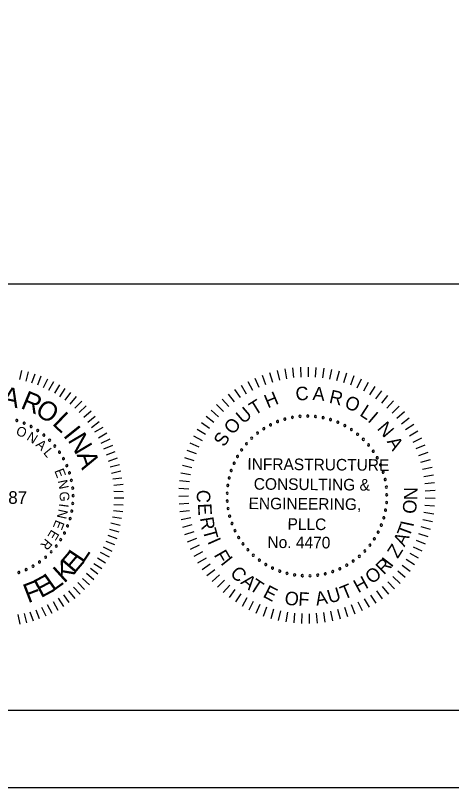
# Model space of a CAD drawing. Extents: x 1970675.2 to 1970711.3, y 796145.2 to 796167.2.
# Drawn here: x 1970699.687 to 1970702.503, y 796145.246 to 796150.229 of the extents above; entities that cross this region are included whole.
import ezdxf

# ---------------------------------------------------------------- set-up
doc = ezdxf.new("R2010")
doc.units = 0
for name, color, linetype in [('BR_BORDER LINES', 7, 'Continuous'), ('BR_TEXT', 7, 'Continuous'), ('Level 31', 7, 'Continuous')]:
    doc.layers.add(name, color=color, linetype=linetype)

msp = doc.modelspace()

# ---------------------------------------------------------------- linework, layer by layer
at = {"layer": 'BR_BORDER LINES'}
for p, q in [((1970697.8703, 796148.4964), (1970703.2355, 796148.4964)), ((1970677.0698, 796145.7463), (1970710.7358, 796145.7463))]:
    msp.add_line(p, q, dxfattribs=at)
at = {"layer": 'BR_TEXT'}
for p, q in [((1970699.7143, 796147.8794), (1970699.7285, 796147.9385)), ((1970701.4262, 796147.9473), (1970701.4372, 796147.8846)), ((1970701.4761, 796147.9545), (1970701.4834, 796147.8913)), ((1970701.5265, 796147.9587), (1970701.5298, 796147.8951)), ((1970701.5769, 796147.9597), (1970701.5764, 796147.8961)), ((1970701.6274, 796147.9577), (1970701.623, 796147.8942)), ((1970701.6776, 796147.9526), (1970701.6693, 796147.8895)), ((1970701.7274, 796147.9445), (1970701.7153, 796147.882)), ((1970699.7554, 796147.8688), (1970699.7713, 796147.9295)), ((1970699.7922, 796147.8582), (1970699.8141, 796147.9155)), ((1970699.8316, 796147.8449), (1970699.8535, 796147.9031)), ((1970701.2334, 796147.8887), (1970701.2593, 796147.8305)), ((1970701.2802, 796147.9077), (1970701.3025, 796147.8481)), ((1970701.328, 796147.9239), (1970701.3466, 796147.863)), ((1970701.3767, 796147.9371), (1970701.3916, 796147.8752)), ((1970701.7767, 796147.9333), (1970701.7608, 796147.8717)), ((1970701.8251, 796147.9192), (1970701.8055, 796147.8586)), ((1970701.8726, 796147.9021), (1970701.8494, 796147.8428)), ((1970699.8675, 796147.8275), (1970699.8954, 796147.883)), ((1970699.9034, 796147.81), (1970699.9347, 796147.8656)), ((1970699.941, 796147.7917), (1970699.9732, 796147.8455)), ((1970701.1439, 796147.8422), (1970701.1766, 796147.7876)), ((1970701.1879, 796147.8668), (1970701.2173, 796147.8103)), ((1970701.919, 796147.8822), (1970701.8922, 796147.8244)), ((1970701.9641, 796147.8594), (1970701.9338, 796147.8034)), ((1970699.9743, 796147.7674), (1970700.0082, 796147.8212)), ((1970700.0075, 796147.7457), (1970700.044, 796147.796)), ((1970701.1014, 796147.8149), (1970701.1374, 796147.7625)), ((1970702.0077, 796147.834), (1970701.974, 796147.78)), ((1970702.0497, 796147.8059), (1970702.0128, 796147.7541)), ((1970700.0399, 796147.7197), (1970700.0806, 796147.7691)), ((1970700.0715, 796147.6945), (1970700.1147, 796147.7388)), ((1970701.0217, 796147.7529), (1970701.0639, 796147.7052)), ((1970701.0606, 796147.7852), (1970701.0998, 796147.735)), ((1970702.0899, 796147.7754), (1970702.0499, 796147.7259)), ((1970702.1281, 796147.7424), (1970702.0852, 796147.6954)), ((1970700.0995, 796147.6668), (1970700.1428, 796147.7102)), ((1970700.9849, 796147.7184), (1970701.0299, 796147.6734)), ((1970702.1643, 796147.7072), (1970702.1186, 796147.6629)), ((1970700.1276, 796147.6357), (1970700.1752, 796147.6774)), ((1970700.1548, 796147.6037), (1970700.2015, 796147.6419)), ((1970700.9179, 796147.643), (1970700.968, 796147.6037)), ((1970700.9502, 796147.6817), (1970700.9979, 796147.6395)), ((1970702.1982, 796147.6699), (1970702.1499, 796147.6284)), ((1970700.1786, 796147.57), (1970700.2278, 796147.6091)), ((1970700.8879, 796147.6023), (1970700.9404, 796147.5662)), ((1970702.2299, 796147.6305), (1970702.1791, 796147.5921)), ((1970702.259, 796147.5893), (1970702.206, 796147.5541)), ((1970700.2006, 796147.5407), (1970700.2532, 796147.5729)), ((1970700.8605, 796147.5599), (1970700.9151, 796147.5271)), ((1970702.2856, 796147.5464), (1970702.2305, 796147.5145)), ((1970700.2226, 796147.5036), (1970700.2761, 796147.5349)), ((1970700.2404, 796147.4691), (1970700.2981, 796147.4961)), ((1970700.8358, 796147.5159), (1970700.8922, 796147.4865)), ((1970702.3095, 796147.5019), (1970702.2526, 796147.4734)), ((1970700.2581, 796147.4321), (1970700.315, 796147.4565)), ((1970700.8137, 796147.4705), (1970700.8719, 796147.4445)), ((1970702.3307, 796147.4561), (1970702.2722, 796147.4311)), ((1970700.2749, 796147.3933), (1970700.3318, 796147.4143)), ((1970700.7945, 796147.4238), (1970700.8541, 796147.4014)), ((1970702.3491, 796147.4091), (1970702.2891, 796147.3877)), ((1970700.2883, 796147.3529), (1970700.346, 796147.3747)), ((1970700.7782, 796147.3761), (1970700.839, 796147.3574)), ((1970702.3645, 796147.361), (1970702.3033, 796147.3433)), ((1970700.2984, 796147.3168), (1970700.3585, 796147.3308)), ((1970700.7648, 796147.3274), (1970700.8267, 796147.3124)), ((1970702.377, 796147.3121), (1970702.3148, 796147.2982)), ((1970700.3066, 796147.2746), (1970700.3668, 796147.2896)), ((1970700.3149, 796147.2385), (1970700.3741, 796147.2458)), ((1970700.7543, 796147.278), (1970700.817, 796147.2668)), ((1970702.3864, 796147.2625), (1970702.3236, 796147.2524)), ((1970700.3214, 796147.1973), (1970700.3824, 796147.2036)), ((1970700.747, 796147.228), (1970700.8102, 796147.2207)), ((1970702.3929, 796147.2124), (1970702.3295, 796147.2062)), ((1970700.3228, 796147.1578), (1970700.3829, 796147.1573)), ((1970700.7426, 796147.1777), (1970700.8062, 796147.1743)), ((1970702.3963, 796147.1621), (1970702.3326, 796147.1597)), ((1970700.325, 796147.1166), (1970700.3859, 796147.1161)), ((1970700.7414, 796147.1273), (1970700.8051, 796147.1277)), ((1970702.3965, 796147.1116), (1970702.3329, 796147.1131)), ((1970700.3221, 796147.0737), (1970700.3822, 796147.0715)), ((1970700.7432, 796147.0768), (1970700.8067, 796147.0812)), ((1970702.3938, 796147.0612), (1970702.3303, 796147.0666)), ((1970700.3129, 796146.994), (1970700.372, 796146.984)), ((1970700.32, 796147.0351), (1970700.3809, 796147.0269)), ((1970700.7481, 796147.0266), (1970700.8113, 796147.0348)), ((1970702.3879, 796147.011), (1970702.3249, 796147.0203)), ((1970700.3039, 796146.9546), (1970700.3639, 796146.9403)), ((1970700.7561, 796146.9767), (1970700.8186, 796146.9888)), ((1970700.7671, 796146.9275), (1970700.8287, 796146.9433)), ((1970702.379, 796146.9613), (1970702.3167, 796146.9744)), ((1970700.295, 796146.9126), (1970700.3549, 796146.8975)), ((1970700.781, 796146.8789), (1970700.8416, 796146.8985)), ((1970702.3671, 796146.9123), (1970702.3057, 796146.9291)), ((1970700.2844, 796146.8758), (1970700.3417, 796146.8538)), ((1970700.7979, 796146.8314), (1970700.8572, 796146.8546)), ((1970702.3522, 796146.864), (1970702.2919, 796146.8846)), ((1970700.2529, 796146.8005), (1970700.3093, 796146.7726)), ((1970700.2704, 796146.8373), (1970700.3268, 796146.8153)), ((1970700.8177, 796146.7849), (1970700.8755, 796146.8117)), ((1970702.3138, 796146.7707), (1970702.2564, 796146.7985)), ((1970702.3344, 796146.8168), (1970702.2755, 796146.841)), ((1970700.2346, 796146.7646), (1970700.2918, 796146.7341)), ((1970700.8403, 796146.7397), (1970700.8963, 796146.77)), ((1970702.2904, 796146.726), (1970702.2348, 796146.7572)), ((1970700.2162, 796146.7279), (1970700.2692, 796146.6957)), ((1970700.8655, 796146.696), (1970700.9196, 796146.7297)), ((1970702.2643, 796146.6828), (1970702.2107, 796146.7173)), ((1970700.1711, 796146.6622), (1970700.2197, 796146.6248)), ((1970700.1936, 796146.6911), (1970700.2457, 796146.659)), ((1970700.8934, 796146.654), (1970700.9453, 796146.6908)), ((1970700.9238, 796146.6137), (1970700.9734, 796146.6536)), ((1970702.2356, 796146.6412), (1970702.1843, 796146.6789)), ((1970700.119, 796146.5956), (1970700.1659, 796146.5541)), ((1970700.1468, 796146.6289), (1970700.1928, 796146.589)), ((1970700.9566, 796146.5753), (1970701.0037, 796146.6182)), ((1970702.1709, 796146.5638), (1970702.1245, 796146.6074)), ((1970702.2044, 796146.6015), (1970702.1555, 796146.6423)), ((1970700.0905, 796146.5701), (1970700.133, 796146.5243)), ((1970700.9917, 796146.539), (1970701.0361, 796146.5847)), ((1970701.0289, 796146.5049), (1970701.0704, 796146.5532)), ((1970702.0973, 796146.4948), (1970702.0566, 796146.5437)), ((1970702.1351, 796146.5281), (1970702.0915, 796146.5745)), ((1970700.03, 796146.5149), (1970700.0699, 796146.4673)), ((1970700.0619, 796146.5403), (1970700.1044, 796146.4936)), ((1970701.0682, 796146.4731), (1970701.1066, 796146.5239)), ((1970701.1093, 796146.4438), (1970701.1446, 796146.4968)), ((1970702.0574, 796146.4637), (1970702.0198, 796146.5151)), ((1970699.9299, 796146.4462), (1970699.9612, 796146.3918)), ((1970699.9635, 796146.4682), (1970699.9966, 796146.4156)), ((1970699.9972, 796146.4894), (1970700.0328, 796146.441)), ((1970701.1521, 796146.4171), (1970701.1841, 796146.4721)), ((1970701.1965, 796146.393), (1970701.225, 796146.4499)), ((1970701.9276, 796146.386), (1970701.9, 796146.4434)), ((1970701.9725, 796146.4093), (1970701.9414, 796146.4648)), ((1970702.0158, 796146.4352), (1970701.9813, 796146.4888)), ((1970699.8558, 796146.4099), (1970699.8827, 796146.3539)), ((1970699.8919, 796146.4267), (1970699.9224, 796146.3707)), ((1970701.2422, 796146.3716), (1970701.2673, 796146.4302)), ((1970701.2892, 796146.3531), (1970701.3106, 796146.4131)), ((1970701.3372, 796146.3375), (1970701.3549, 796146.3986)), ((1970701.7859, 796146.3332), (1970701.7691, 796146.3947)), ((1970701.8342, 796146.3479), (1970701.8137, 796146.4082)), ((1970701.8815, 796146.3656), (1970701.8574, 796146.4245)), ((1970699.7018, 796146.3631), (1970699.715, 796146.3012)), ((1970699.743, 796146.3696), (1970699.758, 796146.3103)), ((1970699.78, 796146.3813), (1970699.801, 796146.3228)), ((1970699.8196, 796146.393), (1970699.8406, 796146.3362)), ((1970701.386, 796146.3248), (1970701.4001, 796146.3869)), ((1970701.4356, 796146.3152), (1970701.4458, 796146.378)), ((1970701.4856, 796146.3086), (1970701.492, 796146.3719)), ((1970701.536, 796146.305), (1970701.5385, 796146.3686)), ((1970701.5865, 796146.3045), (1970701.5851, 796146.3682)), ((1970701.6369, 796146.3071), (1970701.6316, 796146.3706)), ((1970701.6871, 796146.3128), (1970701.6779, 796146.3758)), ((1970701.7368, 796146.3215), (1970701.7238, 796146.3838))]:
    msp.add_line(p, q, dxfattribs=at)
for centre, start, end in [((1970701.4753, 796147.635), 10.6038, 190.6038), ((1970701.5247, 796147.6417), 5.0653, 185.0653), ((1970701.5247, 796147.6417), 185.0653, 5.0653), ((1970701.5745, 796147.6436), 359.5268, 179.5268), ((1970701.5745, 796147.6436), 179.5268, 359.5268), ((1970701.6242, 796147.6407), 173.9884, 353.9884), ((1970701.6242, 796147.6407), 353.9884, 173.9884), ((1970701.6735, 796147.6329), 348.4499, 168.4499), ((1970699.696, 796147.6149), 162.9114, 342.9114), ((1970699.696, 796147.6149), 342.9114, 162.9114), ((1970699.7429, 796147.5979), 157.373, 337.373), ((1970699.7429, 796147.5979), 337.373, 157.373), ((1970701.3343, 796147.587), 27.2191, 207.2191), ((1970701.3343, 796147.587), 207.2191, 27.2191), ((1970701.3797, 796147.6075), 21.6807, 201.6807), ((1970701.3797, 796147.6075), 201.6807, 21.6807), ((1970701.4268, 796147.6235), 16.1422, 196.1422), ((1970701.4268, 796147.6235), 196.1422, 16.1422), ((1970701.4753, 796147.635), 190.6038, 10.6038), ((1970701.6735, 796147.6329), 168.4499, 348.4499), ((1970701.7217, 796147.6205), 162.9114, 342.9114), ((1970701.7217, 796147.6205), 342.9114, 162.9114), ((1970701.7686, 796147.6035), 157.373, 337.373), ((1970701.7686, 796147.6035), 337.373, 157.373), ((1970701.8135, 796147.582), 331.8345, 151.8345), ((1970699.7878, 796147.5764), 151.8345, 331.8345), ((1970699.7878, 796147.5764), 331.8345, 151.8345), ((1970699.8305, 796147.5507), 146.2961, 326.2961), ((1970699.8305, 796147.5507), 326.2961, 146.2961), ((1970701.2504, 796147.5333), 38.2961, 218.2961), ((1970701.291, 796147.5621), 32.7576, 212.7576), ((1970701.291, 796147.5621), 212.7576, 32.7576), ((1970701.8135, 796147.582), 151.8345, 331.8345), ((1970701.8562, 796147.5563), 146.2961, 326.2961), ((1970701.8562, 796147.5563), 326.2961, 146.2961), ((1970699.8705, 796147.521), 140.7576, 320.7576), ((1970699.8705, 796147.521), 320.7576, 140.7576), ((1970699.9075, 796147.4876), 135.2191, 315.2191), ((1970699.9075, 796147.4876), 315.2191, 135.2191), ((1970701.2128, 796147.5006), 43.8345, 223.8345), ((1970701.2128, 796147.5006), 223.8345, 43.8345), ((1970701.2504, 796147.5333), 218.2961, 38.2961), ((1970701.8962, 796147.5266), 140.7576, 320.7576), ((1970701.8962, 796147.5266), 320.7576, 140.7576), ((1970701.9332, 796147.4932), 135.2191, 315.2191), ((1970701.9332, 796147.4932), 315.2191, 135.2191), ((1970699.9411, 796147.4508), 129.6807, 309.6807), ((1970699.9411, 796147.4508), 309.6807, 129.6807), ((1970701.1785, 796147.4645), 49.373, 229.373), ((1970701.1785, 796147.4645), 229.373, 49.373), ((1970701.9668, 796147.4564), 129.6807, 309.6807), ((1970701.9668, 796147.4564), 309.6807, 129.6807), ((1970699.9709, 796147.4109), 124.1422, 304.1422), ((1970699.9709, 796147.4109), 304.1422, 124.1422), ((1970701.1211, 796147.3831), 60.4499, 240.4499), ((1970701.1478, 796147.4252), 54.9114, 234.9114), ((1970701.1478, 796147.4252), 234.9114, 54.9114), ((1970701.9966, 796147.4165), 124.1422, 304.1422), ((1970701.9966, 796147.4165), 304.1422, 124.1422), ((1970699.9968, 796147.3683), 118.6038, 298.6038), ((1970699.9968, 796147.3683), 298.6038, 118.6038), ((1970701.0986, 796147.3387), 65.9884, 245.9884), ((1970701.0986, 796147.3387), 245.9884, 65.9884), ((1970701.1211, 796147.3831), 240.4499, 60.4499), ((1970702.0225, 796147.3739), 118.6038, 298.6038), ((1970702.0225, 796147.3739), 298.6038, 118.6038), ((1970700.0184, 796147.3234), 113.0653, 293.0653), ((1970700.0184, 796147.3234), 293.0653, 113.0653), ((1970701.0804, 796147.2923), 71.5268, 251.5268), ((1970701.0804, 796147.2923), 251.5268, 71.5268), ((1970702.0441, 796147.329), 113.0653, 293.0653), ((1970702.0441, 796147.329), 293.0653, 113.0653), ((1970700.0356, 796147.2766), 107.5268, 287.5268), ((1970700.0356, 796147.2766), 287.5268, 107.5268), ((1970701.0668, 796147.2443), 77.0653, 257.0653), ((1970701.0668, 796147.2443), 257.0653, 77.0653), ((1970702.0613, 796147.2822), 107.5268, 287.5268), ((1970702.0613, 796147.2822), 287.5268, 107.5268), ((1970702.0739, 796147.234), 101.9884, 281.9884), ((1970702.0739, 796147.234), 281.9884, 101.9884), ((1970700.0482, 796147.2284), 101.9884, 281.9884), ((1970700.0482, 796147.2284), 281.9884, 101.9884), ((1970701.0579, 796147.1953), 82.6038, 262.6038), ((1970701.0579, 796147.1953), 262.6038, 82.6038), ((1970702.0818, 796147.1848), 96.4499, 276.4499), ((1970702.0818, 796147.1848), 276.4499, 96.4499), ((1970700.0561, 796147.1792), 96.4499, 276.4499), ((1970700.0561, 796147.1792), 276.4499, 96.4499), ((1970701.0538, 796147.1456), 88.1422, 268.1422), ((1970701.0538, 796147.1456), 268.1422, 88.1422), ((1970702.0849, 796147.1351), 90.9114, 270.9114), ((1970702.0849, 796147.1351), 270.9114, 90.9114), ((1970700.0592, 796147.1295), 90.9114, 270.9114), ((1970700.0592, 796147.1295), 270.9114, 90.9114), ((1970701.0545, 796147.0958), 93.6807, 273.6807), ((1970701.0545, 796147.0958), 273.6807, 93.6807), ((1970702.0832, 796147.0853), 85.373, 265.373), ((1970702.0832, 796147.0853), 265.373, 85.373), ((1970700.0575, 796147.0797), 85.373, 265.373), ((1970700.0575, 796147.0797), 265.373, 85.373), ((1970701.06, 796147.0463), 99.2191, 279.2191), ((1970701.06, 796147.0463), 279.2191, 99.2191), ((1970702.0766, 796147.0359), 79.8345, 259.8345), ((1970702.0766, 796147.0359), 259.8345, 79.8345), ((1970700.0509, 796147.0303), 79.8345, 259.8345), ((1970700.0509, 796147.0303), 259.8345, 79.8345), ((1970701.0703, 796146.9975), 104.7576, 284.7576), ((1970701.0703, 796146.9975), 284.7576, 104.7576), ((1970702.0654, 796146.9873), 74.2961, 254.2961), ((1970702.0654, 796146.9873), 254.2961, 74.2961), ((1970700.0238, 796146.9345), 68.7576, 248.7576), ((1970700.0397, 796146.9817), 74.2961, 254.2961), ((1970700.0397, 796146.9817), 254.2961, 74.2961), ((1970701.0852, 796146.95), 110.2961, 290.2961), ((1970701.0852, 796146.95), 290.2961, 110.2961), ((1970702.0495, 796146.9401), 68.7576, 248.7576), ((1970702.0495, 796146.9401), 248.7576, 68.7576), ((1970700.0034, 796146.889), 63.2191, 243.2191), ((1970700.0034, 796146.889), 243.2191, 63.2191), ((1970700.0238, 796146.9345), 248.7576, 68.7576), ((1970701.1046, 796146.9041), 115.8345, 295.8345), ((1970701.1046, 796146.9041), 295.8345, 115.8345), ((1970702.0291, 796146.8946), 63.2191, 243.2191), ((1970702.0291, 796146.8946), 243.2191, 63.2191), ((1970699.9788, 796146.8457), 57.6807, 237.6807), ((1970699.9788, 796146.8457), 237.6807, 57.6807), ((1970701.1284, 796146.8603), 121.373, 301.373), ((1970701.1284, 796146.8603), 301.373, 121.373), ((1970702.0045, 796146.8513), 57.6807, 237.6807), ((1970702.0045, 796146.8513), 237.6807, 57.6807), ((1970699.9501, 796146.805), 52.1422, 232.1422), ((1970699.9501, 796146.805), 232.1422, 52.1422), ((1970701.1563, 796146.819), 126.9114, 306.9114), ((1970701.1563, 796146.819), 306.9114, 126.9114), ((1970701.9758, 796146.8106), 52.1422, 232.1422), ((1970701.9758, 796146.8106), 232.1422, 52.1422), ((1970699.9175, 796146.7672), 46.6038, 226.6038), ((1970699.9175, 796146.7672), 226.6038, 46.6038), ((1970701.188, 796146.7806), 132.4499, 312.4499), ((1970701.188, 796146.7806), 312.4499, 132.4499), ((1970701.2233, 796146.7454), 137.9884, 317.9884), ((1970701.2233, 796146.7454), 317.9884, 137.9884), ((1970701.9072, 796146.7384), 41.0653, 221.0653), ((1970701.9072, 796146.7384), 221.0653, 41.0653), ((1970701.9432, 796146.7728), 46.6038, 226.6038), ((1970701.9432, 796146.7728), 226.6038, 46.6038), ((1970699.8423, 796146.702), 35.5268, 215.5268), ((1970699.8423, 796146.702), 215.5268, 35.5268), ((1970699.8815, 796146.7328), 41.0653, 221.0653), ((1970699.8815, 796146.7328), 221.0653, 41.0653), ((1970701.2618, 796146.7138), 143.5268, 323.5268), ((1970701.2618, 796146.7138), 323.5268, 143.5268), ((1970701.3032, 796146.6861), 329.0653, 149.0653), ((1970701.8681, 796146.7076), 35.5268, 215.5268), ((1970701.8681, 796146.7076), 215.5268, 35.5268), ((1970699.756, 796146.6524), 24.4499, 204.4499), ((1970699.756, 796146.6524), 204.4499, 24.4499), ((1970699.8004, 796146.6751), 29.9884, 209.9884), ((1970699.8004, 796146.6751), 209.9884, 29.9884), ((1970701.3032, 796146.6861), 149.0653, 329.0653), ((1970701.3471, 796146.6625), 154.6038, 334.6038), ((1970701.3471, 796146.6625), 334.6038, 154.6038), ((1970701.3931, 796146.6432), 160.1422, 340.1422), ((1970701.3931, 796146.6432), 340.1422, 160.1422), ((1970701.7354, 796146.6397), 18.9114, 198.9114), ((1970701.7817, 796146.658), 24.4499, 204.4499), ((1970701.7817, 796146.658), 204.4499, 24.4499), ((1970701.8261, 796146.6807), 29.9884, 209.9884), ((1970701.8261, 796146.6807), 209.9884, 29.9884), ((1970699.7097, 796146.6341), 18.9114, 198.9114), ((1970699.7097, 796146.6341), 198.9114, 18.9114), ((1970701.4407, 796146.6285), 165.6807, 345.6807), ((1970701.4407, 796146.6285), 345.6807, 165.6807), ((1970701.4895, 796146.6184), 171.2191, 351.2191), ((1970701.4895, 796146.6184), 351.2191, 171.2191), ((1970701.539, 796146.6131), 356.7576, 176.7576), ((1970701.539, 796146.6131), 176.7576, 356.7576), ((1970701.5889, 796146.6126), 2.2961, 182.2961), ((1970701.5889, 796146.6126), 182.2961, 2.2961), ((1970701.6385, 796146.6169), 7.8345, 187.8345), ((1970701.6385, 796146.6169), 187.8345, 7.8345), ((1970701.6875, 796146.6259), 13.373, 193.373), ((1970701.6875, 796146.6259), 193.373, 13.373), ((1970701.7354, 796146.6397), 198.9114, 18.9114)]:
    msp.add_arc(centre, 0.00701, start, end, dxfattribs=at)
at = {"layer": 'Level 31'}
msp.add_lwpolyline([(1970675.2365, 796167.2463), (1970675.2365, 796145.2464), (1970711.2364, 796145.2464), (1970711.2364, 796167.2463)], dxfattribs=at)

# ---------------------------------------------------------------- texts
at = {"layer": 'BR_TEXT'}
for s, height, rotation, p in [('A', 0.1241, 348.1981, (1970699.5917, 796147.7163)), ('R', 0.1241, 337.4344, (1970699.715, 796147.6965)), ('H', 0.0872, 22.7882, (1970701.3162, 796147.6927)), ('C', 0.0872, 4.7281, (1970701.499, 796147.7421)), ('A', 0.0872, 355.6981, (1970701.6035, 796147.7471)), ('R', 0.0872, 346.6681, (1970701.7077, 796147.7301)), ('O', 0.1239, 326.5869, (1970699.8072, 796147.6597)), ('T', 0.0872, 31.8182, (1970701.2313, 796147.6451)), ('O', 0.0872, 337.638, (1970701.8055, 796147.7003)), ('U', 0.0872, 40.8482, (1970701.158, 796147.589)), ('L', 0.0872, 327.108, (1970701.9043, 796147.6498)), ('L', 0.1241, 315.9488, (1970699.9198, 796147.5919)), ('I', 0.0872, 319.578, (1970701.9569, 796147.612)), ('O', 0.0872, 49.8782, (1970701.091, 796147.518)), ('N', 0.0872, 310.548, (1970702.0177, 796147.5612)), ('O', 0.0622, 338.4392, (1970699.6851, 796147.5247)), ('N', 0.0622, 328.2042, (1970699.7547, 796147.4933)), ('I', 0.1241, 308.6613, (1970699.9912, 796147.5176)), ('N', 0.1241, 300.7037, (1970700.0218, 796147.4883)), ('S', 0.0872, 58.9083, (1970701.0356, 796147.4398)), ('A', 0.0872, 301.5179, (1970702.0828, 796147.4788)), ('A', 0.0622, 318.657, (1970699.8137, 796147.4532)), ('L', 0.0622, 309.4546, (1970699.8635, 796147.4059)), ('A', 0.1241, 289.4792, (1970700.081, 796147.3952)), ('INFRASTRUCTURE', 0.074771, 359.5268, (1970701.1842, 796147.2972)), ('E', 0.0622, 291.049, (1970699.9373, 796147.2906)), ('CONSULTING &', 0.074771, 359.5268, (1970701.2255, 796147.1686)), ('N', 0.0622, 281.8466, (1970699.9595, 796147.2256)), ('No. 26987', 0.08175, 359.5268, (1970699.2574, 796147.0804)), ('G', 0.0622, 272.2995, (1970699.9713, 796147.1553)), ('C', 0.0872, 267.025, (1970700.8606, 796147.1698)), ('N', 0.0872, 89.2085, (1970702.2821, 796147.1001)), ('ENGINEERING,', 0.074771, 359.5268, (1970701.1919, 796147.0432)), ('O', 0.0872, 83.2085, (1970702.271, 796147.0086)), ('I', 0.0622, 262.4084, (1970699.9709, 796147.0814)), ('E', 0.0872, 273.025, (1970700.865, 796147.0783)), ('N', 0.0622, 257.7339, (1970699.9664, 796147.0468)), ('E', 0.0622, 248.1867, (1970699.9483, 796146.9779)), ('R', 0.0872, 279.025, (1970700.8778, 796146.986)), ('PLLC', 0.07477, 359.5268, (1970701.4436, 796146.9096)), ('T', 0.0872, 69.3954, (1970702.2298, 796146.8568)), ('I', 0.0872, 77.9093, (1970702.2555, 796146.9243)), ('E', 0.0622, 238.9844, (1970699.9204, 796146.9151)), ('T', 0.0872, 285.025, (1970700.8952, 796146.9072)), ('R', 0.0622, 229.782, (1970699.8827, 796146.8577)), ('I', 0.0872, 293.7713, (1970700.9249, 796146.8341)), ('No. 4470', 0.07477, 359.5268, (1970701.3141, 796146.7927)), ('A', 0.0872, 63.3954, (1970702.199, 796146.7965)), ('Z', 0.0872, 57.3954, (1970702.1551, 796146.7202)), ('E', 0.1236, 49.3639, (1970700.0662, 796146.6214)), ('L', 0.1236, 56.4247, (1970700.1237, 796146.6891)), ('F', 0.0872, 299.7713, (1970700.9661, 796146.748)), ('K', 0.1236, 42.3031, (1970700.0009, 796146.5613)), ('I', 0.0872, 308.5268, (1970701.0082, 796146.6942)), ('R', 0.0872, 44.5268, (1970702.0647, 796146.6152)), ('I', 0.0872, 52.3339, (1970702.1141, 796146.6625)), ('C', 0.0872, 314.5268, (1970701.0675, 796146.6241)), ('O', 0.0872, 38.5268, (1970701.9881, 796146.5552)), ('E', 0.1236, 28.1814, (1970699.8506, 796146.4673)), ('L', 0.1236, 35.2422, (1970699.9286, 796146.5097)), ('A', 0.0872, 320.5268, (1970701.1367, 796146.5655)), ('T', 0.0872, 326.5268, (1970701.1911, 796146.527)), ('H', 0.0872, 28.5268, (1970701.9, 796146.4992)), ('F', 0.1236, 21.1206, (1970699.7679, 796146.4348)), ('E', 0.0872, 332.5268, (1970701.2797, 796146.4792)), ('T', 0.0872, 22.5268, (1970701.8068, 796146.4575)), ('O', 0.0872, 350.5268, (1970701.4198, 796146.4304)), ('F', 0.0872, 356.5268, (1970701.5113, 796146.4212)), ('A', 0.0872, 10.5268, (1970701.6312, 796146.4196)), ('U', 0.0872, 16.5268, (1970701.7151, 796146.4331))]:
    msp.add_text(s, height=height, rotation=rotation, dxfattribs=at).set_placement(p)

doc.saveas('drawing.dxf')
